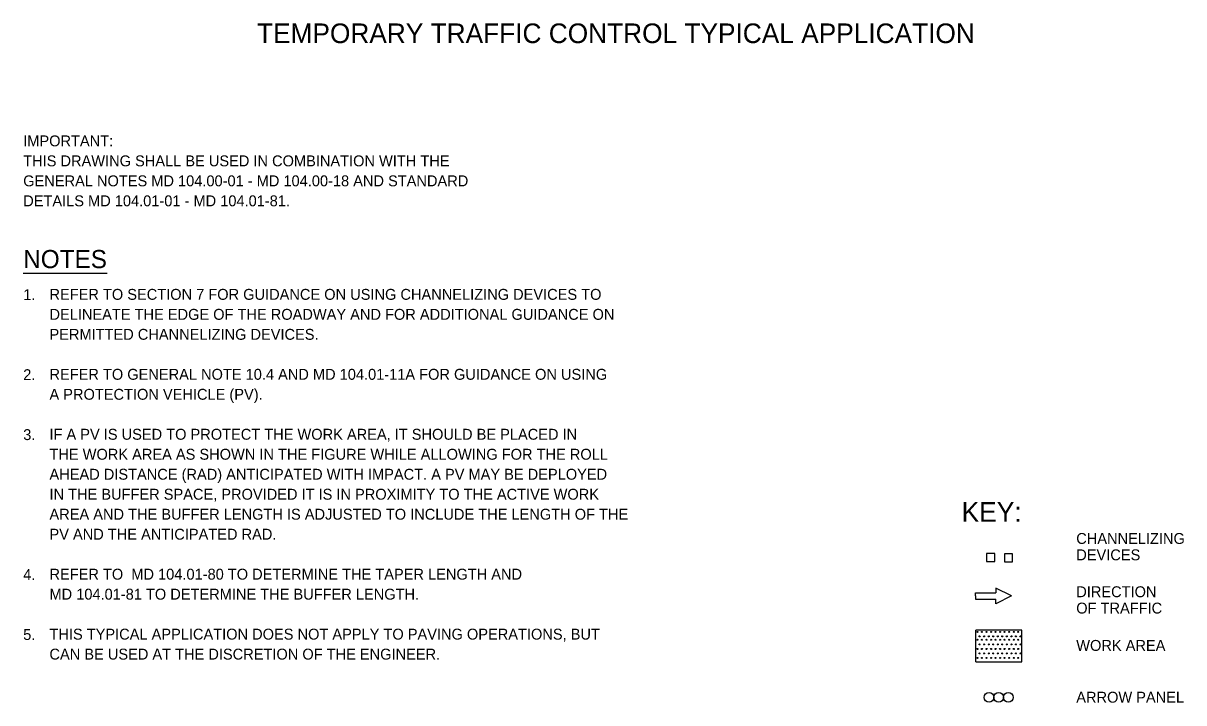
# Model space of a CAD drawing. Extents: x 12.4 to 19.6, y 4 to 16.
# Drawn here: x 12.56 to 18.95, y 12.29 to 16.03 of the extents above; entities that cross this region are included whole.
import ezdxf

# ---------------------------------------------------------------- set-up
doc = ezdxf.new("R2010")
doc.units = 0
for name, color, linetype in [('DETL-LINE', 7, 'Continuous'), ('DETL-NOTE', 7, 'Continuous'), ('DETL-TITL', 7, 'Continuous'), ('USER-BORD', 7, 'Continuous')]:
    doc.layers.add(name, color=color, linetype=linetype)

# ---------------------------------------------------------------- blocks, each defined once
blk = doc.blocks.new('PANEL0')
at = {"layer": 'USER-BORD'}
for centre in [(0.0309, -0.0012), (0.0928, -0.0012), (0.1546, -0.0012)]:
    blk.add_circle(centre, 0.0312, dxfattribs=at)
blk = doc.blocks.new('DIR2')
at = {"layer": 'USER-BORD'}
for p, q in [((0, 0.001), (-0.034, -0.048)), ((0, 0.001), (0.034, -0.048)), ((-0.034, -0.048), (-0.013, -0.048)), ((-0.013, -0.113), (-0.013, -0.048)), ((0.034, -0.048), (0.013, -0.048)), ((0.013, -0.113), (0.013, -0.048)), ((-0.001, -0.113), (-0.013, -0.113)), ((-0.001, -0.113), (0.001, -0.113)), ((0.001, -0.113), (0.013, -0.113))]:
    blk.add_line(p, q, dxfattribs=at)

msp = doc.modelspace()

# ---------------------------------------------------------------- linework, layer by layer
at = {"layer": 'DETL-LINE'}
for p, q in [((12.563, 14.6503), (13.0249, 14.6503)), ((18.0555, 12.6848), (17.8015, 12.6848)), ((18.0555, 12.6848), (17.8015, 12.6848)), ((18.0555, 12.6848), (17.8015, 12.6848)), ((18.0555, 12.6848), (17.8015, 12.6848)), ((17.8017, 12.5107), (17.8017, 12.6848)), ((17.8017, 12.5108), (17.8017, 12.6848)), ((17.8101, 12.6759), (17.8101, 12.6759)), ((17.8109, 12.6759), (17.8109, 12.6759)), ((17.8229, 12.6511), (17.8229, 12.6511)), ((17.8229, 12.6511), (17.8229, 12.6511)), ((17.8357, 12.6759), (17.8357, 12.6759)), ((17.8357, 12.6759), (17.8357, 12.6759)), ((17.8477, 12.6511), (17.8477, 12.6511)), ((17.8477, 12.6511), (17.8477, 12.6511)), ((17.8605, 12.6759), (17.8605, 12.6759)), ((17.8613, 12.6759), (17.8613, 12.6759)), ((17.8733, 12.6511), (17.8733, 12.6511)), ((17.8733, 12.6511), (17.8733, 12.6511)), ((17.8853, 12.6759), (17.8853, 12.6759)), ((17.8861, 12.6759), (17.8861, 12.6759)), ((17.8981, 12.6511), (17.8981, 12.6511)), ((17.8981, 12.6511), (17.8981, 12.6511)), ((17.9101, 12.6759), (17.9101, 12.6759)), ((17.9109, 12.6759), (17.9109, 12.6759)), ((17.9229, 12.6511), (17.9229, 12.6511)), ((17.9229, 12.6511), (17.9229, 12.6511)), ((17.9357, 12.6759), (17.9357, 12.6759)), ((17.9357, 12.6759), (17.9357, 12.6759)), ((17.9477, 12.6511), (17.9477, 12.6511)), ((17.9477, 12.6511), (17.9477, 12.6511)), ((17.9605, 12.6759), (17.9605, 12.6759)), ((17.9605, 12.6759), (17.9605, 12.6759)), ((17.9725, 12.6511), (17.9725, 12.6511)), ((17.9725, 12.6511), (17.9725, 12.6511)), ((17.9853, 12.6759), (17.9853, 12.6759)), ((17.9861, 12.6759), (17.9861, 12.6759)), ((17.9981, 12.6511), (17.9981, 12.6511)), ((17.9981, 12.6511), (17.9981, 12.6511)), ((18.0101, 12.6759), (18.0101, 12.6759)), ((18.0109, 12.6759), (18.0109, 12.6759)), ((18.0229, 12.6511), (18.0229, 12.6511)), ((18.0229, 12.6511), (18.0229, 12.6511)), ((18.0357, 12.6759), (18.0357, 12.6759)), ((18.0357, 12.6759), (18.0357, 12.6759)), ((18.0477, 12.6511), (18.0477, 12.6511)), ((18.0477, 12.6511), (18.0477, 12.6511)), ((18.0555, 12.5108), (18.0555, 12.6848)), ((18.0555, 12.5108), (18.0555, 12.6848)), ((18.0555, 12.5108), (18.0555, 12.6848)), ((18.0555, 12.5108), (18.0555, 12.6848)), ((17.8101, 12.6321), (17.8101, 12.6321)), ((17.8101, 12.5817), (17.8101, 12.5817)), ((17.8109, 12.6321), (17.8109, 12.6321)), ((17.8109, 12.5817), (17.8109, 12.5817)), ((17.8229, 12.6065), (17.8229, 12.6065)), ((17.8357, 12.6321), (17.8357, 12.6321)), ((17.8357, 12.6321), (17.8357, 12.6321)), ((17.8357, 12.5817), (17.8357, 12.5817)), ((17.8357, 12.5817), (17.8357, 12.5817)), ((17.8477, 12.6065), (17.8477, 12.6065)), ((17.8605, 12.6321), (17.8605, 12.6321)), ((17.8605, 12.5817), (17.8605, 12.5817)), ((17.8613, 12.6321), (17.8613, 12.6321)), ((17.8613, 12.5817), (17.8613, 12.5817)), ((17.8733, 12.6065), (17.8733, 12.6065)), ((17.8853, 12.6321), (17.8853, 12.6321)), ((17.8853, 12.5817), (17.8853, 12.5817)), ((17.8861, 12.6321), (17.8861, 12.6321)), ((17.8861, 12.5817), (17.8861, 12.5817)), ((17.8981, 12.6065), (17.8981, 12.6065)), ((17.9101, 12.6321), (17.9101, 12.6321)), ((17.9101, 12.5817), (17.9101, 12.5817)), ((17.9109, 12.6321), (17.9109, 12.6321)), ((17.9109, 12.5817), (17.9109, 12.5817)), ((17.9229, 12.6065), (17.9229, 12.6065)), ((17.9357, 12.6321), (17.9357, 12.6321)), ((17.9357, 12.6321), (17.9357, 12.6321)), ((17.9357, 12.5817), (17.9357, 12.5817)), ((17.9357, 12.5817), (17.9357, 12.5817)), ((17.9477, 12.6065), (17.9477, 12.6065)), ((17.9605, 12.6321), (17.9605, 12.6321)), ((17.9605, 12.6321), (17.9605, 12.6321)), ((17.9605, 12.5817), (17.9605, 12.5817)), ((17.9605, 12.5817), (17.9605, 12.5817)), ((17.9725, 12.6065), (17.9725, 12.6065)), ((17.9853, 12.6321), (17.9853, 12.6321)), ((17.9853, 12.5817), (17.9853, 12.5817)), ((17.9861, 12.6321), (17.9861, 12.6321)), ((17.9861, 12.5817), (17.9861, 12.5817)), ((17.9981, 12.6065), (17.9981, 12.6065)), ((18.0101, 12.6321), (18.0101, 12.6321)), ((18.0101, 12.5817), (18.0101, 12.5817)), ((18.0109, 12.6321), (18.0109, 12.6321)), ((18.0109, 12.5817), (18.0109, 12.5817)), ((18.0229, 12.6065), (18.0229, 12.6065)), ((18.0357, 12.6321), (18.0357, 12.6321)), ((18.0357, 12.6321), (18.0357, 12.6321)), ((18.0357, 12.5817), (18.0357, 12.5817)), ((18.0357, 12.5817), (18.0357, 12.5817)), ((18.0477, 12.6065), (18.0477, 12.6065)), ((17.8101, 12.5325), (17.8101, 12.5325)), ((17.8109, 12.5325), (17.8109, 12.5325)), ((17.8229, 12.5569), (17.8229, 12.5569)), ((17.8229, 12.5569), (17.8229, 12.5569)), ((17.8357, 12.5325), (17.8357, 12.5325)), ((17.8357, 12.5325), (17.8357, 12.5325)), ((17.8477, 12.5569), (17.8477, 12.5569)), ((17.8477, 12.5569), (17.8477, 12.5569)), ((17.8605, 12.5325), (17.8605, 12.5325)), ((17.8613, 12.5325), (17.8613, 12.5325)), ((17.8733, 12.5569), (17.8733, 12.5569)), ((17.8733, 12.5569), (17.8733, 12.5569)), ((17.8853, 12.5325), (17.8853, 12.5325)), ((17.8861, 12.5325), (17.8861, 12.5325)), ((17.8981, 12.5569), (17.8981, 12.5569)), ((17.8981, 12.5569), (17.8981, 12.5569)), ((17.9101, 12.5325), (17.9101, 12.5325)), ((17.9109, 12.5325), (17.9109, 12.5325)), ((17.9229, 12.5569), (17.9229, 12.5569)), ((17.9229, 12.5569), (17.9229, 12.5569)), ((17.9357, 12.5325), (17.9357, 12.5325)), ((17.9357, 12.5325), (17.9357, 12.5325)), ((17.9477, 12.5569), (17.9477, 12.5569)), ((17.9477, 12.5569), (17.9477, 12.5569)), ((17.9605, 12.5325), (17.9605, 12.5325)), ((17.9605, 12.5325), (17.9605, 12.5325)), ((17.9725, 12.5569), (17.9725, 12.5569)), ((17.9725, 12.5569), (17.9725, 12.5569)), ((17.9853, 12.5325), (17.9853, 12.5325)), ((17.9861, 12.5325), (17.9861, 12.5325)), ((17.9981, 12.5569), (17.9981, 12.5569)), ((17.9981, 12.5569), (17.9981, 12.5569)), ((18.0101, 12.5325), (18.0101, 12.5325)), ((18.0109, 12.5325), (18.0109, 12.5325)), ((18.0229, 12.5569), (18.0229, 12.5569)), ((18.0229, 12.5569), (18.0229, 12.5569)), ((18.0357, 12.5325), (18.0357, 12.5325)), ((18.0357, 12.5325), (18.0357, 12.5325)), ((18.0477, 12.5569), (18.0477, 12.5569)), ((18.0477, 12.5569), (18.0477, 12.5569)), ((17.8017, 12.5107), (18.0556, 12.5107))]:
    msp.add_line(p, q, dxfattribs=at)
for points in [[(17.8612, 13.0628), (17.906, 13.0628), (17.906, 13.1076), (17.8612, 13.1076)], [(17.9601, 13.061), (18.0049, 13.061), (18.0049, 13.1058), (17.9601, 13.1058)]]:
    msp.add_lwpolyline(points, close=True, dxfattribs=at)
for centre in [(17.811, 12.6758), (17.823, 12.651), (17.8358, 12.6758), (17.8478, 12.651), (17.8614, 12.6758), (17.8734, 12.651), (17.8862, 12.6758), (17.8982, 12.651), (17.911, 12.6758), (17.923, 12.651), (17.9358, 12.6758), (17.9478, 12.651), (17.9606, 12.6758), (17.9726, 12.651), (17.9862, 12.6758), (17.9982, 12.651), (18.011, 12.6758), (18.023, 12.651), (18.0358, 12.6758), (18.0478, 12.651), (17.811, 12.6321), (17.811, 12.5817), (17.823, 12.6065), (17.8358, 12.6321), (17.8358, 12.5817), (17.8478, 12.6065), (17.8614, 12.6321), (17.8614, 12.5817), (17.8734, 12.6065), (17.8862, 12.6321), (17.8862, 12.5817), (17.8982, 12.6065), (17.911, 12.6321), (17.911, 12.5817), (17.923, 12.6065), (17.9358, 12.6321), (17.9358, 12.5817), (17.9478, 12.6065), (17.9606, 12.6321), (17.9606, 12.5817), (17.9726, 12.6065), (17.9862, 12.6321), (17.9862, 12.5817), (17.9982, 12.6065), (18.011, 12.6321), (18.011, 12.5817), (18.023, 12.6065), (18.0358, 12.6321), (18.0358, 12.5817), (18.0478, 12.6065), (17.811, 12.5324), (17.823, 12.5569), (17.8358, 12.5324), (17.8478, 12.5569), (17.8614, 12.5324), (17.8734, 12.5569), (17.8862, 12.5324), (17.8982, 12.5569), (17.911, 12.5324), (17.923, 12.5569), (17.9358, 12.5324), (17.9478, 12.5569), (17.9606, 12.5324), (17.9726, 12.5569), (17.9862, 12.5324), (17.9982, 12.5569), (18.011, 12.5324), (18.023, 12.5569), (18.0358, 12.5324), (18.0478, 12.5569)]:
    msp.add_circle(centre, 0.00291, dxfattribs=at)

# ---------------------------------------------------------------- block references
at = {"layer": 'DETL-LINE', "xscale": 1.2917647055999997, "yscale": 1.7223529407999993, "rotation": -90}
msp.add_blockref('DIR2', (17.9959, 12.8732), dxfattribs=at)
at = {"layer": 'DETL-LINE', "xscale": 0.8611764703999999, "yscale": 0.8611764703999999}
msp.add_blockref('PANEL0', (17.8482, 12.3164), dxfattribs=at)

# ---------------------------------------------------------------- texts
at = {"layer": 'DETL-NOTE'}
for s, height, p in [('IMPORTANT:', 0.06, (12.563, 15.3479)), ('THIS DRAWING SHALL BE USED IN COMBINATION WITH THE ', 0.06, (12.563, 15.2379)), ('GENERAL NOTES MD 104.00-01 - MD 104.00-18 AND STANDARD ', 0.06, (12.563, 15.1279)), ('DETAILS MD 104.01-01 - MD 104.01-81. ', 0.06, (12.563, 15.0179)), ('NOTES', 0.1, (12.563, 14.6775)), ('1.', 0.06, (12.563, 14.5013)), ('REFER TO SECTION 7 FOR GUIDANCE ON USING CHANNELIZING DEVICES TO ', 0.06, (12.7074, 14.5032)), ('DELINEATE THE EDGE OF THE ROADWAY AND FOR ADDITIONAL GUIDANCE ON ', 0.06, (12.7074, 14.3932)), ('PERMITTED CHANNELIZING DEVICES.', 0.06, (12.7074, 14.2832)), ('2.', 0.06, (12.563, 14.0613)), ('REFER TO GENERAL NOTE 10.4 AND MD 104.01-11A FOR GUIDANCE ON USING ', 0.06, (12.7074, 14.0632)), ('A PROTECTION VEHICLE (PV).', 0.06, (12.7074, 13.9532)), ('3.', 0.06, (12.563, 13.7313)), ('IF A PV IS USED TO PROTECT THE WORK AREA, IT SHOULD BE PLACED IN ', 0.06, (12.7074, 13.7332)), ('THE WORK AREA AS SHOWN IN THE FIGURE WHILE ALLOWING FOR THE ROLL ', 0.06, (12.7074, 13.6232)), ('AHEAD DISTANCE (RAD) ANTICIPATED WITH IMPACT. A PV MAY BE DEPLOYED ', 0.06, (12.7074, 13.5132)), ('IN THE BUFFER SPACE, PROVIDED IT IS IN PROXIMITY TO THE ACTIVE WORK ', 0.06, (12.7074, 13.4032)), ('AREA AND THE BUFFER LENGTH IS ADJUSTED TO INCLUDE THE LENGTH OF THE ', 0.06, (12.7074, 13.2932)), ('PV AND THE ANTICIPATED RAD.', 0.06, (12.7074, 13.1832)), ('CHANNELIZING', 0.06, (18.3547, 13.1597)), ('DEVICES', 0.06, (18.3547, 13.0697)), ('REFER TO  MD 104.01-80 TO DETERMINE THE TAPER LENGTH AND ', 0.06, (12.7074, 12.9632)), ('4.', 0.06, (12.563, 12.9613)), ('MD 104.01-81 TO DETERMINE THE BUFFER LENGTH.', 0.06, (12.7074, 12.8532)), ('DIRECTION', 0.06, (18.3547, 12.8666)), ('OF TRAFFIC', 0.06, (18.3547, 12.7766)), ('5.', 0.06, (12.563, 12.6313)), ('THIS TYPICAL APPLICATION DOES NOT APPLY TO PAVING OPERATIONS, BUT ', 0.06, (12.7074, 12.6332)), ('CAN BE USED AT THE DISCRETION OF THE ENGINEER.', 0.06, (12.7074, 12.5232)), ('WORK AREA', 0.06, (18.3547, 12.5712)), ('ARROW PANEL', 0.06, (18.3547, 12.2862))]:
    msp.add_text(s, height=height, dxfattribs=at).set_placement(p)
at = {"layer": 'DETL-TITL'}
for s, height, p in [('TEMPORARY TRAFFIC CONTROL TYPICAL APPLICATION', 0.108, (13.8488, 15.916)), ('KEY:', 0.10852, (17.724, 13.2816))]:
    msp.add_text(s, height=height, dxfattribs=at).set_placement(p)

doc.saveas('drawing.dxf')
